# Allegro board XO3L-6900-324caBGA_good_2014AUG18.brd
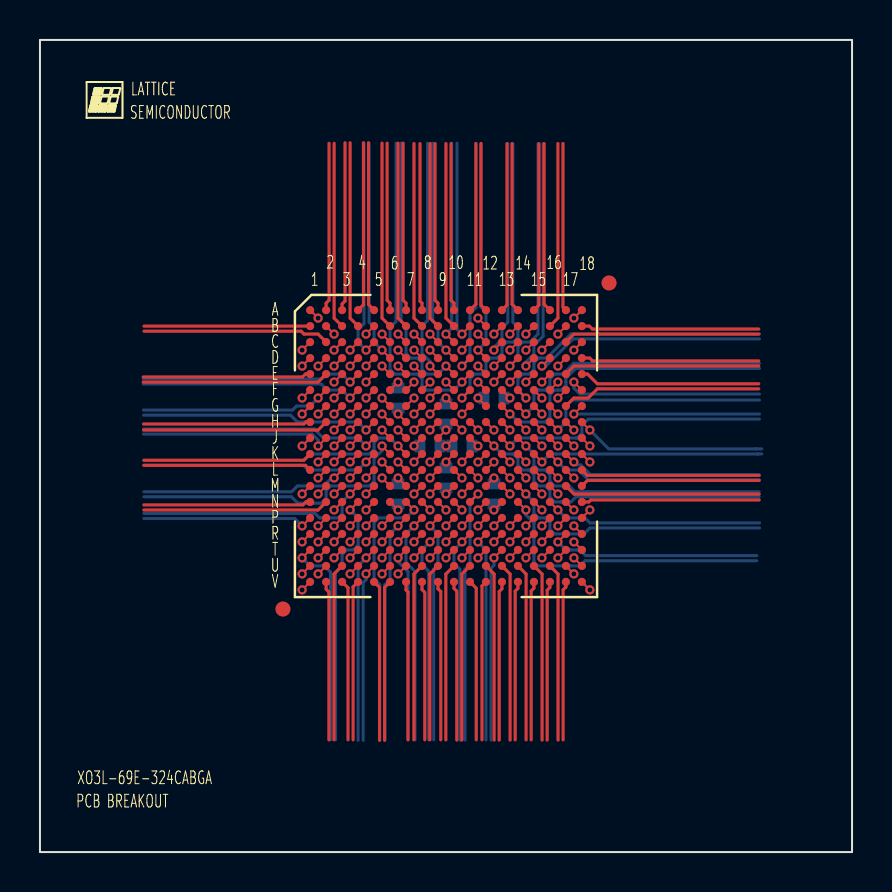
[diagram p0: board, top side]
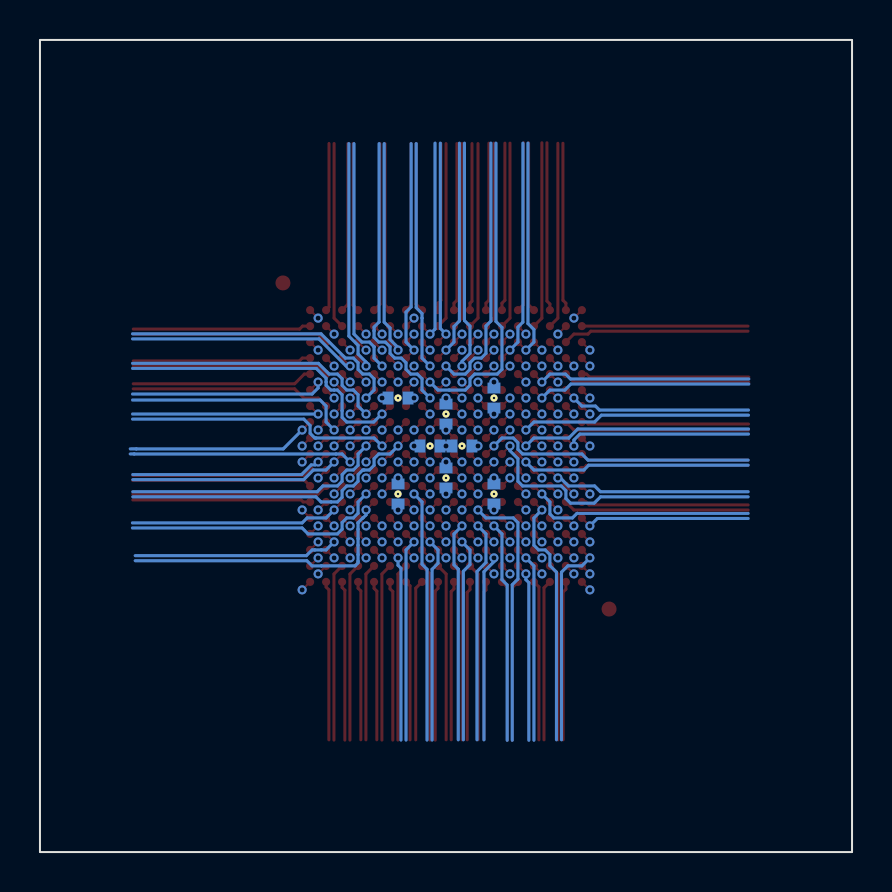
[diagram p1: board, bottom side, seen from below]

Outline 40.64 x 40.64 mm; copper layers: TOP, L2_GND, L3_SIGNAL, L4_SIGNAL, L5_PWR, BOTTOM. Coordinates in mm from the lower left corner of the outline.
Outline path: rectangle 0,0 40.64,40.64

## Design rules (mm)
net group CDPB4: nets PB4C PB4D
net group CDPB6: nets PB6C PB6D
net group CDPB7: nets PB7C PB7D
net group CDPB9: nets PB9C PB9D
net group CDPB13: nets PB13C PB13D
net group CDPB15: nets PB15C PB15D
net group CDPB16: nets PB16C PB16D
net group CDPB18: nets PB18C PB18D
net group CDPB21: nets PB21C PB21D
net group CDPB23: nets PB23C PB23D
net group CDPB26: nets PB26C PB26D
net group CDPB31: nets PB31C PB31D
net group CDPB35: nets PB35C PB35D
net group CDPB37: nets PB37C PB37D
net group CDPB38: nets PB38C PB38D
net group CDPL2: nets PL2C PL2D
net group CDPL3: nets PL3C PL3D
net group CDPL4: nets PL4C PL4D
net group CDPL5: nets PL5C PL5D
net group CDPL6: nets PL6C PL6D
net group CDPL7: nets PL7C PL7D
net group CDPL9: nets PL9C PL9D
net group CDPL10: nets PL10C PL10D
net group CDPL15: nets PL15C PL15D
net group CDPL16: nets PL16C PL16D
net group CDPL18: nets PL18C PL18D
net group CDPL19: nets PL19C PL19D
net group CDPL21: nets PL21C PL21D
net group CDPL23: nets PL23C PL23D
net group CDPL24: nets PL24C PL24D
net group CDPL25: nets PL25C PL25D
net group CDPR2: nets PR2C PR2D
net group CDPR3: nets PR3C PR3D
net group CDPR4: nets PR4C PR4D
net group CDPR6: nets PR6C PR6D
net group CDPR7: nets PR7C PR7D
net group CDPR8: nets PR8C PR8D
net group CDPR10: nets PR10C PR10D
net group CDPR11: nets PR11C PR11D
net group CDPR16: nets PR16C PR16D
net group CDPR17: nets PR17C PR17D
net group CDPR19: nets PR19C PR19D
net group CDPR21: nets PR21C PR21D
net group CDPR22: nets PR22C PR22D
net group CDPR23: nets PR23C PR23D
net group CDPR24: nets PR24C PR24D
net group CDPR25: nets PR25C PR25D
net group CDPT9: nets PT9C PT9D
net group CDPT10: nets PT10C PT10D
net group CDPT11: nets PT11C PT11D
net group CDPT14: nets PT14C PT14D
net group CDPT17: nets PT17C PT17D
net group CDPT18: nets PT18C PT18D
net group CDPT21: nets PT21C PT21D
net group CDPT22: nets PT22C PT22D
net group CDPT25: nets PT25C PT25D
net group CDPT26: nets PT26C PT26D
net group CDPT27: nets PT27C PT27D
net group CDPT33: nets PT33C PT33D
net group CDPT34: nets PT34C PT34D
net group CDPT35: nets PT35C PT35D
net group CDPT36: nets PT36C PT36D
net group PB4: nets PB4A PB4B
net group PB6: nets PB6A PB6B
net group PB7: nets PB7A PB7B
net group PB9: nets PB9A PB9B
net group PB10: nets PB10A PB10B
net group PB12: nets PB12A PB12B
net group PB13: nets PB13A PB13B
net group PB15: nets PB15A PB15B
net group PB16: nets PB16A PB16B
net group PB18: nets PB18A PB18B
net group PB21: nets PB21A PB21B
net group PB23: nets PB23A PB23B
net group PB26: nets PB26A PB26B
net group PB28: nets PB28A PB28B
net group PB29: nets PB29A PB29B
net group PB31: nets PB31A PB31B
net group PB32: nets PB32A PB32B
net group PB34: nets PB34A PB34B
net group PB35: nets PB35A PB35B
net group PB37: nets PB37A PB37B
net group PB38: nets PB38A PB38B
net group PL2: nets PL2A PL2B
net group PL3: nets PL3A PL3B
net group PL4: nets PL4A PL4B
net group PL5: nets PL5A PL5B
net group PL6: nets PL6A PL6B
net group PL8: nets PL8A PL8B
net group PL9: nets PL9A PL9B
net group PL10: nets PL10A PL10B
net group PL11: nets PL11A PL11B
net group PL12: nets PL12A PL12B
net group PL15: nets PL15A PL15B
net group PL17: nets PL17A PL17B
net group PL18: nets PL18A PL18B
net group PL19: nets PL19A PL19B
net group PL22: nets PL22A PL22B
net group PL23: nets PL23A PL23B
net group PL24: nets PL24A PL24B
net group PL25: nets PL25A PL25B
net group PR2: nets PR2A PR2B
net group PR3: nets PR3A PR3B
net group PR4: nets PR4A PR4B
net group PR5: nets PR5A PR5B
net group PR7: nets PR7A PR7B
net group PR8: nets PR8A PR8B
net group PR9: nets PR9A PR9B
net group PR11: nets PR11A PR11B
net group PR12: nets PR12A PR12B
net group PR15: nets PR15A PR15B
net group PR16: nets PR16A PR16B
net group PR17: nets PR17A PR17B
net group PR18: nets PR18A PR18B
net group PR21: nets PR21A PR21B
net group PR22: nets PR22A PR22B
net group PR23: nets PR23A PR23B
net group PR24: nets PR24A PR24B
net group PR25: nets PR25A PR25B
net group PT9: nets PT9A PT9B
net group PT10: nets PT10A PT10B
net group PT11: nets PT11A PT11B
net group PT12: nets PT12A PT12B
net group PT13: nets PT13A PT13B
net group PT14: nets PT14A PT14B
net group PT15: nets PT15A PT15B
net group PT16: nets PT16A PT16B
net group PT17: nets PT17A PT17B
net group PT18: nets PT18A PT18B
net group PT21: nets PT21A PT21B
net group PT22: nets PT22A PT22B
net group PT25: nets PT25A PT25B
net group PT26: nets PT26A PT26B
net group PT27: nets PT27A PT27B
net group PT28: nets PT28A PT28B
net group PT32: nets PT32A PT32B
net group PT33: nets PT33A PT33B
net group PT34: nets PT34A PT34B
net group PT35: nets PT35A PT35B
net group PT36: nets PT36A PT36B

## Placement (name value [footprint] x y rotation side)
BGA  -  [BGA324C80P18X18_1500X1500X17-1]  20.32 20.32 270 top
C1  VAL  [C0402]  17.92 22.72 90 bottom
C2  VAL  [C0402]  20.32 21.92 270 bottom
C3  VAL  [C0402]  22.72 17.92 270 bottom
C4  VAL  [C0402]  22.72 22.72 0 bottom
C5  VAL  [C0402]  19.52 20.32 0 bottom
C6  VAL  [C0402]  21.12 20.32 180 bottom
C7  VAL  [C0402]  20.32 18.72 90 bottom
C8  VAL  [C0402]  17.92 17.92 270 bottom
NOREF  -  []  24.69 13 0 top

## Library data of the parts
BGA = BGA324C80P18X18_1500X1500X17-1
C1-C8 = C0402: User Part Number: UPN; Tolerance: TOL

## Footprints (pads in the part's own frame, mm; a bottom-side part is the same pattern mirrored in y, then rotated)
BGA324C80P18X18_1500X1500X17-1
  round 0.75 smd: (-8.16,8.16) (8.16,-8.16)
  round 0.406 smd: A1(-6.8,-6.8) A2(-6.8,-6) A3(-6.8,-5.2) A4(-6.8,-4.4) A5(-6.8,-3.6) A6(-6.8,-2.8) A7(-6.8,-2) A8(-6.8,-1.2) A9(-6.8,-0.4) A10(-6.8,0.4) A11(-6.8,1.2) A12(-6.8,2) A13(-6.8,2.8) A14(-6.8,3.6) A15(-6.8,4.4) A16(-6.8,5.2) A17(-6.8,6) A18(-6.8,6.8) B1(-6,-6.8) B2(-6,-6) B3(-6,-5.2) B4(-6,-4.4) B5(-6,-3.6) B6(-6,-2.8) B7(-6,-2) B8(-6,-1.2) B9(-6,-0.4) B10(-6,0.4) B11(-6,1.2) B12(-6,2) B13(-6,2.8) B14(-6,3.6) B15(-6,4.4) B16(-6,5.2) B17(-6,6) B18(-6,6.8) C1(-5.2,-6.8) C2(-5.2,-6) C3(-5.2,-5.2) C4(-5.2,-4.4) C5(-5.2,-3.6) C6(-5.2,-2.8) C7(-5.2,-2) C8(-5.2,-1.2) C9(-5.2,-0.4) C10(-5.2,0.4) C11(-5.2,1.2) C12(-5.2,2) C13(-5.2,2.8) C14(-5.2,3.6) C15(-5.2,4.4) C16(-5.2,5.2) C17(-5.2,6) C18(-5.2,6.8) D1(-4.4,-6.8) D2(-4.4,-6) D3(-4.4,-5.2) D4(-4.4,-4.4) D5(-4.4,-3.6) D6(-4.4,-2.8) D7(-4.4,-2) D8(-4.4,-1.2) D9(-4.4,-0.4) D10(-4.4,0.4) D11(-4.4,1.2) D12(-4.4,2) D13(-4.4,2.8) D14(-4.4,3.6) D15(-4.4,4.4) D16(-4.4,5.2) D17(-4.4,6) D18(-4.4,6.8) E1(-3.6,-6.8) E2(-3.6,-6) E3(-3.6,-5.2) E4(-3.6,-4.4) E5(-3.6,-3.6) E6(-3.6,-2.8) E7(-3.6,-2) E8(-3.6,-1.2) E9(-3.6,-0.4) E10(-3.6,0.4) E11(-3.6,1.2) E12(-3.6,2) E13(-3.6,2.8) E14(-3.6,3.6) E15(-3.6,4.4) E16(-3.6,5.2) E17(-3.6,6) E18(-3.6,6.8) F1(-2.8,-6.8) F2(-2.8,-6) F3(-2.8,-5.2) F4(-2.8,-4.4) F5(-2.8,-3.6) F6(-2.8,-2.8) F7(-2.8,-2) F8(-2.8,-1.2) F9(-2.8,-0.4) F10(-2.8,0.4) F11(-2.8,1.2) F12(-2.8,2) F13(-2.8,2.8) F14(-2.8,3.6) F15(-2.8,4.4) F16(-2.8,5.2) F17(-2.8,6) F18(-2.8,6.8) G1(-2,-6.8) G2(-2,-6) G3(-2,-5.2) G4(-2,-4.4) G5(-2,-3.6) G6(-2,-2.8) G7(-2,-2) G8(-2,-1.2) G9(-2,-0.4) G10(-2,0.4) G11(-2,1.2) G12(-2,2) G13(-2,2.8) G14(-2,3.6) G15(-2,4.4) G16(-2,5.2) G17(-2,6) G18(-2,6.8) H1(-1.2,-6.8) H2(-1.2,-6) H3(-1.2,-5.2) H4(-1.2,-4.4) H5(-1.2,-3.6) H6(-1.2,-2.8) H7(-1.2,-2) H8(-1.2,-1.2) H9(-1.2,-0.4) H10(-1.2,0.4) H11(-1.2,1.2) H12(-1.2,2) H13(-1.2,2.8) H14(-1.2,3.6) H15(-1.2,4.4) H16(-1.2,5.2) H17(-1.2,6) H18(-1.2,6.8) J1(-0.4,-6.8) J2(-0.4,-6) J3(-0.4,-5.2) J4(-0.4,-4.4) J5(-0.4,-3.6) J6(-0.4,-2.8) J7(-0.4,-2) J8(-0.4,-1.2) J9(-0.4,-0.4) J10(-0.4,0.4) J11(-0.4,1.2) J12(-0.4,2) J13(-0.4,2.8) J14(-0.4,3.6) J15(-0.4,4.4) J16(-0.4,5.2) J17(-0.4,6) J18(-0.4,6.8) K1(0.4,-6.8) K2(0.4,-6) K3(0.4,-5.2) K4(0.4,-4.4) K5(0.4,-3.6) K6(0.4,-2.8) K7(0.4,-2) K8(0.4,-1.2) K9(0.4,-0.4) K10(0.4,0.4) K11(0.4,1.2) K12(0.4,2) K13(0.4,2.8) K14(0.4,3.6) K15(0.4,4.4) K16(0.4,5.2) K17(0.4,6) K18(0.4,6.8) L1(1.2,-6.8) L2(1.2,-6) L3(1.2,-5.2) L4(1.2,-4.4) L5(1.2,-3.6) L6(1.2,-2.8) L7(1.2,-2) L8(1.2,-1.2) L9(1.2,-0.4) L10(1.2,0.4) L11(1.2,1.2) L12(1.2,2) L13(1.2,2.8) L14(1.2,3.6) L15(1.2,4.4) L16(1.2,5.2) L17(1.2,6) L18(1.2,6.8) M1(2,-6.8) M2(2,-6) M3(2,-5.2) M4(2,-4.4) M5(2,-3.6) M6(2,-2.8) M7(2,-2) M8(2,-1.2) M9(2,-0.4) M10(2,0.4) M11(2,1.2) M12(2,2) M13(2,2.8) M14(2,3.6) M15(2,4.4) M16(2,5.2) M17(2,6) M18(2,6.8) N1(2.8,-6.8) N2(2.8,-6) N3(2.8,-5.2) N4(2.8,-4.4) N5(2.8,-3.6) N6(2.8,-2.8) N7(2.8,-2) N8(2.8,-1.2) N9(2.8,-0.4) N10(2.8,0.4) N11(2.8,1.2) N12(2.8,2) N13(2.8,2.8) N14(2.8,3.6) N15(2.8,4.4) N16(2.8,5.2) N17(2.8,6) N18(2.8,6.8) P1(3.6,-6.8) P2(3.6,-6) P3(3.6,-5.2) P4(3.6,-4.4) P5(3.6,-3.6) P6(3.6,-2.8) P7(3.6,-2) P8(3.6,-1.2) P9(3.6,-0.4) P10(3.6,0.4) P11(3.6,1.2) P12(3.6,2) P13(3.6,2.8) P14(3.6,3.6) P15(3.6,4.4) P16(3.6,5.2) P17(3.6,6) P18(3.6,6.8) R1(4.4,-6.8) R2(4.4,-6) R3(4.4,-5.2) R4(4.4,-4.4) R5(4.4,-3.6) R6(4.4,-2.8) R7(4.4,-2) R8(4.4,-1.2) R9(4.4,-0.4) R10(4.4,0.4) R11(4.4,1.2) R12(4.4,2) R13(4.4,2.8) R14(4.4,3.6) R15(4.4,4.4) R16(4.4,5.2) R17(4.4,6) R18(4.4,6.8) T1(5.2,-6.8) T2(5.2,-6) T3(5.2,-5.2) T4(5.2,-4.4) T5(5.2,-3.6) T6(5.2,-2.8) T7(5.2,-2) T8(5.2,-1.2) T9(5.2,-0.4) T10(5.2,0.4) T11(5.2,1.2) T12(5.2,2) T13(5.2,2.8) T14(5.2,3.6) T15(5.2,4.4) T16(5.2,5.2) T17(5.2,6) T18(5.2,6.8) U1(6,-6.8) U2(6,-6) U3(6,-5.2) U4(6,-4.4) U5(6,-3.6) U6(6,-2.8) U7(6,-2) U8(6,-1.2) U9(6,-0.4) U10(6,0.4) U11(6,1.2) U12(6,2) U13(6,2.8) U14(6,3.6) U15(6,4.4) U16(6,5.2) U17(6,6) U18(6,6.8) V1(6.8,-6.8) V2(6.8,-6) V3(6.8,-5.2) V4(6.8,-4.4) V5(6.8,-3.6) V6(6.8,-2.8) V7(6.8,-2) V8(6.8,-1.2) V9(6.8,-0.4) V10(6.8,0.4) V11(6.8,1.2) V12(6.8,2) V13(6.8,2.8) V14(6.8,3.6) V15(6.8,4.4) V16(6.8,5.2) V17(6.8,6) V18(6.8,6.8)
C0402
  rect 0.54x0.64 smd: 1(-0.5,0) 2(0.5,0)

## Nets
GND: BGA.A1 BGA.A18 BGA.B2 BGA.B17 BGA.F6 BGA.F13 BGA.J9 BGA.J10 BGA.K9 BGA.K10 BGA.N6 BGA.N13 BGA.U2 BGA.U17 BGA.V1 BGA.V18 C1.2 C2.2 C3.2 C4.2 C5.2 C6.2 C7.2 C8.2
VCC: BGA.G12 BGA.H8 BGA.H9 BGA.H10 BGA.H11 BGA.L8 BGA.L9 BGA.L10 BGA.L11 BGA.M12 C3.1 C4.1
VCCIO0: BGA.G8 BGA.G9 BGA.G10 BGA.G11 C2.1
VCCIO1: BGA.H12 BGA.J11 BGA.K11 BGA.L12 C6.1
VCCIO2: BGA.M8 BGA.M9 BGA.M10 BGA.M11 C7.1
VCCIO3: BGA.L7 BGA.M7 C8.1
VCCIO4: BGA.J8 BGA.K8 C5.1
VCCIO5: BGA.G7 BGA.H7 C1.1
PB4A: BGA.V2
PB4B: BGA.U3
PB4C: BGA.R4
PB4D: BGA.P6
PB6A: BGA.T3
PB6B: BGA.U4
PB6C: BGA.P5
PB6D: BGA.R6
PB7A: BGA.V3
PB7B: BGA.V4
PB7C: BGA.R5
PB7D: BGA.T4
PB9A: BGA.T5
PB9B: BGA.U5
PB9C: BGA.N7
PB9D: BGA.P7
PB10A: BGA.N8
PB10B: BGA.R7
PB12A: BGA.T6
PB12B: BGA.U6
PB13A: BGA.V5
PB13B: BGA.V6
PB13C: BGA.T7
PB13D: BGA.P8
PB15A: BGA.V7
PB15B: BGA.U8
PB15C: BGA.U7
PB15D: BGA.R8
PB16A: BGA.T8
PB16B: BGA.T9
PB16C: BGA.R9
PB16D: BGA.P9
PB18A: BGA.V8
PB18B: BGA.U9
PB18C: BGA.N9
PB18D: BGA.N10
PB21A: BGA.V9
PB21B: BGA.U10
PB21C: BGA.T10
PB21D: BGA.R10
PB23A: BGA.V10
PB23B: BGA.U11
PB23C: BGA.P10
PB23D: BGA.T11
PB26A: BGA.V11
PB26B: BGA.V12
PB26C: BGA.N11
PB26D: BGA.R11
PB28A: BGA.P11
PB28B: BGA.T12
PB29A: BGA.U12
PB29B: BGA.V13
PB31A: BGA.U13
PB31B: BGA.V14
PB31C: BGA.R12
PB31D: BGA.T13
PB32A: BGA.T14
PB32B: BGA.N12
PB34A: BGA.U14
PB34B: BGA.V15
PB35A: BGA.U15
PB35B: BGA.V16
PB35C: BGA.P12
PB35D: BGA.R14
PB37A: BGA.T15
PB37B: BGA.T16
PB37C: BGA.R13
PB37D: BGA.R15
PB38A: BGA.U16
PB38B: BGA.V17
PB38C: BGA.P13
PB38D: BGA.P14
PL2A: BGA.B1
PL2B: BGA.C2
PL2C: BGA.D3
PL2D: BGA.C1
PL3A: BGA.E4
PL3B: BGA.F4
PL3C: BGA.E3
PL3D: BGA.F5
PL4A: BGA.D2
PL4B: BGA.G5
PL4C: BGA.F3
PL4D: BGA.D1
PL5A: BGA.E2
PL5B: BGA.E1
PL5C: BGA.F2
PL5D: BGA.H5
PL6A: BGA.G4
PL6B: BGA.G3
PL6C: BGA.F1
PL6D: BGA.G6
PL7C: BGA.H3
PL7D: BGA.H4
PL8A: BGA.G2
PL8B: BGA.G1
PL9A: BGA.H2
PL9B: BGA.H1
PL9C: BGA.H6
PL9D: BGA.J1
PL10A: BGA.J2
PL10B: BGA.J5
PL10C: BGA.J3
PL10D: BGA.J7
PL11A: BGA.J4
PL11B: BGA.K3
PL12A: BGA.K2
PL12B: BGA.J6
PL15A: BGA.K1
PL15B: BGA.L1
PL15C: BGA.K7
PL15D: BGA.K5
PL16C: BGA.K6
PL16D: BGA.L3
PL17A: BGA.K4
PL17B: BGA.L2
PL18A: BGA.L4
PL18B: BGA.M2
PL18C: BGA.M1
PL18D: BGA.L6
PL19A: BGA.N1
PL19B: BGA.N2
PL19C: BGA.M3
PL19D: BGA.L5
PL21C: BGA.M5
PL21D: BGA.N3
PL22A: BGA.P1
PL22B: BGA.M4
PL23A: BGA.R1
PL23B: BGA.P3
PL23C: BGA.P2
PL23D: BGA.M6
PL24A: BGA.N4
PL24B: BGA.T1
PL24C: BGA.R2
PL24D: BGA.U1
PL25A: BGA.T2
PL25B: BGA.N5
PL25C: BGA.P4
PL25D: BGA.R3
PR2A: BGA.B18
PR2B: BGA.C17
PR2C: BGA.F14
PR2D: BGA.D16
PR3A: BGA.E15
PR3B: BGA.C18
PR3C: BGA.G13
PR3D: BGA.G14
PR4A: BGA.F15
PR4B: BGA.D17
PR4C: BGA.E16
PR4D: BGA.H13
PR5A: BGA.G15
PR5B: BGA.F16
PR6C: BGA.E17
PR6D: BGA.D18
PR7A: BGA.G16
PR7B: BGA.H15
PR7C: BGA.H14
PR7D: BGA.F17
PR8A: BGA.E18
PR8B: BGA.G17
PR8C: BGA.H16
PR8D: BGA.F18
PR9A: BGA.J15
PR9B: BGA.H17
PR10C: BGA.J13
PR10D: BGA.G18
PR11A: BGA.J16
PR11B: BGA.J17
PR11C: BGA.J14
PR11D: BGA.J12
PR12A: BGA.H18
PR12B: BGA.K15
PR15A: BGA.K14
PR15B: BGA.J18
PR16A: BGA.K16
PR16B: BGA.K17
PR16C: BGA.K12
PR16D: BGA.K13
PR17A: BGA.K18
PR17B: BGA.L16
PR17C: BGA.L15
PR17D: BGA.L13
PR18A: BGA.L17
PR18B: BGA.M16
PR19C: BGA.L18
PR19D: BGA.M18
PR21A: BGA.M17
PR21B: BGA.N18
PR21C: BGA.L14
PR21D: BGA.N17
PR22A: BGA.M15
PR22B: BGA.P18
PR22C: BGA.M14
PR22D: BGA.N16
PR23A: BGA.P17
PR23B: BGA.N15
PR23C: BGA.R18
PR23D: BGA.M13
PR24A: BGA.P16
PR24B: BGA.T18
PR24C: BGA.R17
PR24D: BGA.N14
PR25A: BGA.P15
PR25B: BGA.U18
PR25C: BGA.R16
PR25D: BGA.T17
PT9A: BGA.A2
PT9B: BGA.B3
PT9C: BGA.D4
PT9D: BGA.E5
PT10A: BGA.C3
PT10B: BGA.C4
PT10C: BGA.F7
PT10D: BGA.E6
PT11A: BGA.A3
PT11B: BGA.B4
PT11C: BGA.D5
PT11D: BGA.B5
PT12A: BGA.A4
PT12B: BGA.A5
PT13A: BGA.C5
PT13B: BGA.D6
PT14A: BGA.B6
PT14B: BGA.A6
PT14C: BGA.D7
PT14D: BGA.C6
PT15A: BGA.A7
PT15B: BGA.B7
PT16A: BGA.D8
PT16B: BGA.E7
PT17A: BGA.B8
PT17B: BGA.A8
PT17C: BGA.C7
PT17D: BGA.C8
PT18A: BGA.A9
PT18B: BGA.B9
PT18C: BGA.E8
PT18D: BGA.F8
PT21A: BGA.A10
PT21B: BGA.B10
PT21C: BGA.C9
PT21D: BGA.D9
PT22A: BGA.C10
PT22B: BGA.B11
PT22C: BGA.E9
PT22D: BGA.D10
PT25A: BGA.B12
PT25B: BGA.C11
PT25C: BGA.F9
PT25D: BGA.F10
PT26A: BGA.A11
PT26B: BGA.A12
PT26C: BGA.E10
PT26D: BGA.E11
PT27A: BGA.C12
PT27B: BGA.B13
PT27C: BGA.D11
PT27D: BGA.D12
PT28A: BGA.A13
PT28B: BGA.A14
PT32A: BGA.F11
PT32B: BGA.C13
PT33A: BGA.B14
PT33B: BGA.B15
PT33C: BGA.E12
PT33D: BGA.F12
PT34A: BGA.C14
PT34B: BGA.C15
PT34C: BGA.D13
PT34D: BGA.E13
PT35A: BGA.A15
PT35B: BGA.A16
PT35C: BGA.D14
PT35D: BGA.D15
PT36A: BGA.B16
PT36B: BGA.A17
PT36C: BGA.C16
PT36D: BGA.E14

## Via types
v1: diameter 0.457, hole 0.254, TOP to BOTTOM, 254 vias

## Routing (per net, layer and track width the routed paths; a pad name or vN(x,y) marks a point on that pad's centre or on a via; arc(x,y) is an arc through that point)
GND: length 11.5
  TOP w0.102: BGA.J10 v1(20.32,20.32) ; BGA.U2 v1(13.92,13.92) ; BGA.V18 v1(27.52,13.12) ; BGA.A1 v1(13.92,26.72) ; BGA.J9 v1(20.32,21.12) ; BGA.U17 v1(26.72,13.92) ; BGA.N6 v1(17.92,17.12) ; BGA.B2 v1(14.72,25.92) ; BGA.F13 v1(23.52,22.72) ; BGA.F6 v1(17.92,23.52) ; BGA.K10 v1(20.32,19.52) ; BGA.B17 v1(25.92,25.92) ; BGA.N13 v1(22.72,17.12) ; BGA.A18 v1(26.72,26.72) ; BGA.K9 v1(19.52,19.52) ; BGA.V1 v1(13.12,13.12)
  BOTTOM w0.102: C3.2 v1(22.72,17.12) ; C1.2 v1(17.92,23.52) ; C6.2 v1(20.32,20.32) C5.2 ; C2.2 v1(20.32,21.12) ; C7.2 v1(20.32,19.52) ; C4.2 v1(23.52,22.72) ; C8.2 v1(17.92,17.12)
VCC: length 6.3
  TOP w0.102: BGA.H9 v1(19.52,21.12) ; BGA.L9 v1(19.52,18.72) ; BGA.L10 v1(21.12,18.72) ; BGA.L11 v1(21.92,18.72) ; BGA.M12 v1(22.72,18.72) ; BGA.H8 v1(18.72,21.12) ; BGA.L8 v1(18.72,18.72) ; BGA.H10 v1(21.12,21.12) ; BGA.H11 v1(21.92,21.12) ; BGA.G12 v1(21.92,22.72)
  BOTTOM w0.102: C4.1 v1(21.92,22.72) ; C3.1 v1(22.72,18.72)
VCCIO0: length 2.6
  TOP w0.102: BGA.G9 v1(19.52,21.92) ; BGA.G11 v1(21.12,21.92) ; BGA.G10 v1(20.32,22.72) ; BGA.G8 v1(18.72,21.92)
  BOTTOM w0.102: C2.1 v1(20.32,22.72)
VCCIO1: length 2.6
  TOP w0.102: BGA.K11 v1(21.12,19.52) ; BGA.J11 v1(21.92,20.32) ; BGA.H12 v1(22.72,21.12) ; BGA.L12 v1(22.72,19.52)
  BOTTOM w0.102: C6.1 v1(21.92,20.32)
VCCIO2: length 2.6
  TOP w0.102: BGA.M10 v1(20.32,17.92) ; BGA.M11 v1(21.12,17.92) ; BGA.M8 v1(18.72,17.92) ; BGA.M9 v1(19.52,17.92)
  BOTTOM w0.102: C7.1 v1(20.32,17.92)
VCCIO3: length 1.4
  TOP w0.102: BGA.M7 v1(17.92,18.72) ; BGA.L7 v1(17.92,19.52)
  BOTTOM w0.102: v1(17.92,18.72) C8.1
VCCIO4: length 1.4
  TOP w0.102: BGA.K8 v1(18.72,19.52) ; BGA.J8 v1(18.72,20.32)
  BOTTOM w0.102: v1(18.72,20.32) C5.1
VCCIO5: length 1.4
  TOP w0.102: BGA.H7 v1(17.92,21.92) ; BGA.G7 v1(18.72,22.72)
  BOTTOM w0.102: C1.1 v1(17.92,21.92)
PB4A: length 8
  TOP w0.152: 14.46,5.62 14.46,13.01 14.32,13.15 BGA.V2
PB4B: length 8.9
  TOP w0.152: 14.71,5.62 14.71,13.91 BGA.U3
PB4C: length 10.7
  TOP w0.102: BGA.R4 v1(15.52,15.52)
  L3_SIGNAL w0.152: 16.2,5.64 16.2,13.47 15.92,13.75 15.92,15.12 v1(15.52,15.52)
PB4D: length 12
  TOP w0.102: BGA.P6 v1(17.12,16.32)
  L3_SIGNAL w0.152: 16.45,5.64 16.45,13.45 16.72,13.72 16.72,14.89 16.95,15.12 17.02,15.12 17.29,15.12 17.52,15.35 17.52,15.92 v1(17.12,16.32)
PB6A: length 9.9
  TOP w0.102: BGA.T3 v1(14.72,14.72)
  L3_SIGNAL w0.152: v1(14.72,14.72) 14.92,14.52 14.92,14.3 14.81,14.19 14.56,13.94 14.56,5.65
PB6B: length 9.7
  TOP w0.102: BGA.U4 v1(15.52,13.92)
  L3_SIGNAL w0.152: v1(15.52,13.92) 15.32,14.12 15.1,14.12 14.99,14.01 14.82,13.84 14.82,5.65
PB6C: length 11.6
  TOP w0.102: BGA.P5 v1(16.32,16.32)
  L4_SIGNAL w0.152: 17,5.59 17,13.35 16.72,13.64 16.72,15.92 v1(16.32,16.32)
PB6D: length 10.8
  TOP w0.102: BGA.R6 v1(17.12,15.52)
  L4_SIGNAL w0.152: 17.26,5.59 17.26,13.31 17.52,13.58 17.52,14.55 17.52,15.11 17.12,15.51 v1(17.12,15.52)
PB7A: length 8
  TOP w0.152: 15.42,5.62 15.42,13.22 BGA.V3
PB7B: length 8
  TOP w0.152: BGA.V4 15.67,13.27 15.67,5.62
PB7C: length 10.8
  TOP w0.102: BGA.R5 v1(16.32,15.52)
  L4_SIGNAL w0.152: v1(16.32,15.52) 16.17,15.52 15.92,15.27 15.92,13.61 15.72,13.41 15.72,5.59
PB7D: length 10
  TOP w0.102: BGA.T4 v1(15.52,14.72)
  L4_SIGNAL w0.152: 15.45,5.62 15.45,13.33 15.12,13.66 15.12,14.32 v1(15.52,14.72)
PB9A: length 9.9
  TOP w0.102: BGA.T5 v1(16.32,14.72)
  BOTTOM w0.152: v1(16.32,14.72) 15.92,14.32 15.92,5.59
PB9B: length 9
  TOP w0.102: BGA.U5 v1(16.32,13.92)
  BOTTOM w0.152: v1(16.32,13.92) 16.32,13.63 16.17,13.48 16.17,5.59
PB9C: length 13.8
  TOP w0.102: BGA.N7 v1(18.72,17.12)
  BOTTOM w0.152: 17.01,5.59 17.01,13.38 16.72,13.66 16.72,16.49 16.95,16.72 18.32,16.72 v1(18.72,17.12)
PB9D: length 11.6
  TOP w0.102: BGA.P7 v1(17.92,16.32)
  BOTTOM w0.152: v1(17.92,16.32) 17.52,15.92 17.52,13.63 17.26,13.37 17.26,5.59
PB10A: length 12.4
  TOP w0.102: BGA.N8 v1(19.52,17.12)
  L4_SIGNAL w0.152: v1(19.52,17.12) 19.12,16.72 19.12,14.35 18.86,14.09 18.86,5.59
PB10B: length 10.8
  TOP w0.102: BGA.R7 v1(17.92,15.52)
  L4_SIGNAL w0.152: v1(17.92,15.52) 18.32,15.12 18.32,14.37 18.6,14.09 18.6,5.59
PB12A: length 9.9
  TOP w0.102: BGA.T6 v1(17.12,14.72)
  L3_SIGNAL w0.152: v1(17.12,14.72) 17.52,14.32 17.52,13.56 17.37,13.42 17.37,5.59
PB12B: length 8.9
  TOP w0.102: v1(17.12,13.92) BGA.U6
  L3_SIGNAL w0.152: v1(17.12,13.92) 17.12,5.59
PB13A: length 8
  TOP w0.152: BGA.V5 16.99,13.25 16.99,5.59
PB13B: length 8
  TOP w0.152: 17.25,5.59 17.25,13.25 BGA.V6
PB13C: length 9.9
  TOP w0.102: BGA.T7 v1(17.92,14.72)
  BOTTOM w0.152: v1(17.92,14.72) 17.92,14.53 18.42,14.03 18.42,5.62
PB13D: length 11.6
  TOP w0.102: BGA.P8 v1(18.72,16.32)
  BOTTOM w0.152: v1(18.72,16.32) 18.32,15.92 18.32,14.49 18.77,14.04 18.77,5.62
PB15A: length 7.9
  TOP w0.152: 18.42,5.62 18.42,13.01 18.32,13.11 BGA.V7
PB15B: length 8.9
  TOP w0.152: BGA.U8 18.71,13.91 18.71,5.62
PB15C: length 8.9
  TOP w0.102: v1(17.92,13.92) BGA.U7
  L3_SIGNAL w0.152: 18.07,5.63 18.07,13.44 17.92,13.59 v1(17.92,13.92)
PB15D: length 10.6
  TOP w0.102: BGA.R8 v1(18.72,15.52)
  L3_SIGNAL w0.152: v1(18.72,15.52) 18.32,15.12 18.32,5.63
PB16A: length 9.8
  TOP w0.102: BGA.T8 v1(18.72,14.72)
  L3_SIGNAL w0.152: 18.97,5.63 18.97,14.47 v1(18.72,14.72)
PB16B: length 9.8
  TOP w0.102: BGA.T9 v1(19.52,14.72)
  L3_SIGNAL w0.152: v1(19.52,14.72) 19.23,14.43 19.23,5.63
PB16C: length 10.8
  TOP w0.102: BGA.R9 v1(19.52,15.52)
  BOTTOM w0.152: 19.45,5.62 19.45,14.05 19.12,14.38 19.12,15.12 v1(19.52,15.52)
PB16D: length 11.5
  TOP w0.102: BGA.P9 v1(19.52,16.32)
  BOTTOM w0.152: v1(19.52,16.32) 19.92,15.92 19.92,14.37 19.71,14.16 19.71,5.62
PB18A: length 8
  TOP w0.152: 19.26,5.62 19.26,12.99 19.12,13.13 BGA.V8
PB18B: length 8.9
  TOP w0.152: 19.51,5.62 19.51,13.91 BGA.U9
PB18C: length 12.4
  TOP w0.102: BGA.N9 v1(20.32,17.12)
  L4_SIGNAL w0.152: 20.22,5.62 20.22,14.18 19.92,14.48 19.92,16.32 19.92,16.32 19.92,16.72 v1(20.32,17.12)
PB18D: length 12.3
  TOP w0.102: BGA.N10 v1(21.12,17.12)
  L4_SIGNAL w0.152: v1(21.12,17.12) 20.72,16.72 20.72,14.37 20.47,14.12 20.47,5.62
PB21A: length 8
  TOP w0.152: 20.06,5.62 20.06,13.04 19.92,13.17 BGA.V9
PB21B: length 8.9
  TOP w0.152: BGA.U10 20.31,13.91 20.31,5.62
PB21C: length 9.7
  TOP w0.102: BGA.T10 v1(20.32,14.72)
  L3_SIGNAL w0.152: 20.17,5.63 20.17,14.28 20.32,14.43 v1(20.32,14.72)
PB21D: length 10.6
  TOP w0.102: BGA.R10 v1(20.32,15.52)
  L3_SIGNAL w0.152: 19.92,5.63 19.92,14.41 19.92,15.12 v1(20.32,15.52)
PB23A: length 8
  TOP w0.152: 20.86,5.6 20.86,13.06 20.72,13.19 BGA.V10
PB23B: length 8.9
  TOP w0.152: 21.11,5.6 21.11,13.91 BGA.U11
PB23C: length 11.4
  TOP w0.102: BGA.P10 v1(20.32,16.32)
  L3_SIGNAL w0.152: 20.72,5.63 20.72,15.92 v1(20.32,16.32)
PB23D: length 9.7
  TOP w0.102: BGA.T11 v1(21.12,14.72)
  L3_SIGNAL w0.152: 20.97,5.63 20.97,14.23 21.12,14.37 v1(21.12,14.72)
PB26A: length 8
  TOP w0.152: BGA.V11 21.83,13.21 21.83,5.62
PB26B: length 8
  TOP w0.152: 22.12,5.62 22.12,13.32 BGA.V12
PB26C: length 13.2
  TOP w0.102: BGA.N11 v1(21.92,17.92)
  BOTTOM w0.152: v1(21.92,17.92) BGA.N11 21.52,14.4 21.27,14.15 21.27,5.6
PB26D: length 10.8
  TOP w0.102: BGA.R11 v1(21.12,15.52)
  BOTTOM w0.152: v1(21.12,15.52) 20.72,15.12 20.72,14.45 21.02,14.15 21.02,5.6
PB28A: length 11.4
  TOP w0.102: BGA.P11 v1(21.12,16.32)
  L3_SIGNAL w0.152: v1(21.12,16.32) 21.52,15.92 21.52,14.33 21.52,5.6
PB28B: length 9.7
  TOP w0.102: BGA.T12 v1(21.92,14.72)
  L3_SIGNAL w0.152: 21.77,5.6 21.77,14.22 21.92,14.37 v1(21.92,14.72)
PB29A: length 8.9
  TOP w0.152: BGA.U12 22.73,13.91 22.73,5.6
PB29B: length 8
  TOP w0.152: 22.98,5.6 22.98,13.04 23.12,13.17 BGA.V13
PB31A: length 8.9
  TOP w0.152: BGA.U13 23.53,13.91 23.53,5.6
PB31B: length 8
  TOP w0.152: 23.78,5.62 23.78,13.06 23.92,13.19 BGA.V14
PB31C: length 10.6
  TOP w0.102: BGA.R12 v1(21.92,15.52)
  BOTTOM w0.152: v1(21.92,15.52) 22.32,15.12 22.32,5.6
PB31D: length 9.7
  TOP w0.102: BGA.T13 v1(22.72,14.72)
  BOTTOM w0.152: 22.57,5.6 22.57,14.2 22.72,14.35 v1(22.72,14.72)
PB32A: length 9.8
  TOP w0.102: BGA.T14 v1(23.52,14.72)
  L3_SIGNAL w0.152: v1(23.52,14.72) 23.52,14.12 23.32,13.92 23.32,5.6
PB32B: length 12.6
  TOP w0.102: BGA.N12 v1(21.92,17.12)
  L3_SIGNAL w0.152: v1(21.92,17.12) 22.32,16.72 22.32,14.55 22.55,14.32 22.57,14.32 23.07,13.82 23.07,5.6
PB34A: length 8.9
  TOP w0.152: 24.33,5.62 24.33,13.91 BGA.U14
PB34B: length 8
  TOP w0.152: 24.58,5.62 24.58,13.07 24.72,13.2 BGA.V15
PB35A: length 8.9
  TOP w0.152: 25.13,5.6 25.13,13.91 BGA.U15
PB35B: length 8
  TOP w0.152: BGA.V16 25.52,13.24 25.38,13.1 25.38,5.6
PB35C: length 11.6
  TOP w0.102: BGA.P12 v1(21.92,16.32)
  L4_SIGNAL w0.152: 21.82,5.62 21.82,14.02 21.52,14.32 21.52,15.92 v1(21.92,16.32)
PB35D: length 12.2
  TOP w0.102: BGA.R14 v1(23.52,15.52)
  L4_SIGNAL w0.152: 22.07,5.62 22.07,14.03 22.32,14.28 22.32,15.69 22.55,15.92 23.12,15.92 v1(23.52,15.52)
PB37A: length 9.8
  TOP w0.102: BGA.T15 v1(24.32,14.72)
  L4_SIGNAL w0.152: 24.58,5.61 24.58,14.46 v1(24.32,14.72)
PB37B: length 9.8
  TOP w0.102: BGA.T16 v1(25.12,14.72)
  L4_SIGNAL w0.152: 24.83,5.61 24.83,14.43 v1(25.12,14.72)
PB37C: length 10.7
  TOP w0.102: BGA.R13 v1(22.72,15.52)
  L4_SIGNAL w0.152: 23.37,5.6 23.37,14.19 23.12,14.44 23.12,15.12 v1(22.72,15.52)
PB37D: length 10.8
  TOP w0.102: BGA.R15 v1(24.32,15.52)
  L4_SIGNAL w0.152: 23.62,5.62 23.62,14.16 23.92,14.46 23.92,15.12 v1(24.32,15.52)
PB38A: length 8.9
  TOP w0.152: 25.93,5.6 25.93,13.91 BGA.U16
PB38B: length 8
  TOP w0.152: BGA.V17 26.32,13.26 26.18,13.13 26.18,5.62
PB38C: length 12.1
  TOP w0.102: BGA.P13 v1(22.72,16.32)
  L3_SIGNAL w0.152: v1(22.72,16.32) 23.12,15.92 23.12,15.69 23.12,15.35 23.35,15.12 23.77,15.12 23.92,14.97 23.92,14.32 24.22,14.02 24.22,5.63
PB38D: length 12.2
  TOP w0.102: BGA.P14 v1(23.52,16.32)
  L3_SIGNAL w0.152: 24.47,5.63 24.47,14.02 24.72,14.27 24.72,15.72 24.52,15.92 24.49,15.92 24.49,15.92 24.15,15.92 24.15,15.92 23.92,15.92 v1(23.52,16.32)
PL2A: length 8.3
  TOP w0.152: BGA.B1 5.21,26.32
PL2B: length 9.3
  TOP w0.152: BGA.C2 13.92,25.92 13.22,25.92 13.07,26.07 5.21,26.07
PL2C: length 10.2
  TOP w0.102: BGA.D3 v1(14.72,24.32)
  L3_SIGNAL w0.152: 5.21,24.72 14.32,24.72 v1(14.72,24.32)
PL2D: length 8.5
  TOP w0.102: BGA.C1 v1(13.12,25.12)
  L3_SIGNAL w0.152: 5.21,24.97 12.71,24.97 12.85,25.12 v1(13.12,25.12)
PL3A: length 11.2
  TOP w0.102: BGA.E4 v1(15.52,23.52)
  BOTTOM w0.152: v1(15.52,23.52) 15.12,23.92 14.34,23.92 14.09,23.67 5.17,23.67
PL3B: length 11.2
  TOP w0.102: BGA.F4 v1(15.52,22.72)
  BOTTOM w0.152: 5.17,23.42 14.07,23.42 14.37,23.12 15.12,23.12 v1(15.52,22.72)
PL3C: length 10.1
  TOP w0.102: BGA.E3 v1(14.72,23.52)
  L3_SIGNAL w0.152: v1(14.72,23.52) 5.17,23.52
PL3D: length 12.5
  TOP w0.102: BGA.F5 v1(16.32,22.72)
  L3_SIGNAL w0.152: 5.17,23.77 14.15,23.77 14.3,23.92 14.89,23.92 15.12,23.69 15.12,23.35 15.35,23.12 15.92,23.12 v1(16.32,22.72)
PL4A: length 10.4
  TOP w0.102: BGA.D2 v1(13.92,24.32)
  L4_SIGNAL w0.152: 5.21,25.22 12.39,25.22 12.79,25.62 13.27,25.62 13.92,24.97 v1(13.92,24.32)
PL4B: length 13.7
  TOP w0.102: BGA.G5 v1(16.32,21.92)
  L4_SIGNAL w0.152: 5.21,24.97 12.37,24.97 12.62,24.72 12.97,24.72 13.29,24.72 13.52,24.49 13.52,24.15 13.75,23.92 14.5,23.92 14.89,23.92 15.12,23.69 15.12,23.35 15.35,23.12 15.69,23.12 15.92,22.89 15.92,22.32 v1(16.32,21.92)
PL4C: length 10.4
  TOP w0.102: BGA.F3 v1(14.72,22.72)
  L4_SIGNAL w0.152: 5.17,23.35 14.09,23.35 v1(14.72,22.72)
PL4D: length 9
  TOP w0.102: BGA.D1 v1(13.12,24.32)
  L4_SIGNAL w0.152: 5.17,23.6 12.8,23.6 13.12,23.92 v1(13.12,24.32)
PL5A: length 9.3
  TOP w0.152: BGA.E2 13.92,23.52 5.17,23.52
PL5B: length 8.4
  TOP w0.152: BGA.E1 13.28,23.92 13.14,23.77 5.17,23.77
PL5C: length 9.6
  TOP w0.102: BGA.F2 v1(13.92,22.72)
  BOTTOM w0.152: 5.18,22.12 12.64,22.12 12.84,22.32 13.52,22.32 v1(13.92,22.72)
PL5D: length 12
  TOP w0.102: BGA.H5 v1(16.32,21.12)
  BOTTOM w0.152: 5.18,21.86 12.54,21.86 12.88,21.52 15.92,21.52 v1(16.32,21.12)
PL6A: length 11.2
  TOP w0.102: BGA.G4 v1(15.52,21.92)
  L4_SIGNAL w0.152: v1(15.52,21.92) 15.12,21.52 12.76,21.52 12.53,21.75 5.18,21.75
PL6B: length 10.4
  TOP w0.102: BGA.G3 v1(14.72,21.92)
  L4_SIGNAL w0.102: 14.72,21.92 v1(14.72,21.92)
  L4_SIGNAL w0.152: 5.18,22 12.55,22 12.87,22.32 14.32,22.32 v1(14.72,21.92)
PL6C: length 8.5
  TOP w0.102: BGA.F1 v1(13.12,22.72)
  L3_SIGNAL w0.152: v1(13.12,22.72) 5.18,22.72
PL6D: length 13.3
  TOP w0.102: BGA.G6 v1(17.12,22.72)
  L3_SIGNAL w0.152: v1(17.12,22.72) 16.72,22.32 14.55,22.32 14.32,22.55 14.32,22.89 14.09,23.12 12.81,23.12 12.67,22.97 5.18,22.97
PL7C: length 10.2
  TOP w0.102: BGA.H3 v1(14.72,21.12)
  L3_SIGNAL w0.152: v1(14.72,21.12) 14.45,21.12 14.3,21.27 5.18,21.27
PL7D: length 11.1
  TOP w0.102: BGA.H4 v1(15.52,21.12)
  L3_SIGNAL w0.152: 5.18,21.52 15.12,21.52 15.52,21.12 v1(15.52,21.12)
PL8A: length 9.5
  TOP w0.102: BGA.G2 v1(13.92,21.92)
  L3_SIGNAL w0.152: v1(13.92,21.92) 13.69,21.92 13.29,22.32 5.18,22.32
PL8B: length 8.6
  TOP w0.102: BGA.G1 v1(13.12,21.92)
  L3_SIGNAL w0.152: v1(13.12,21.92) 12.91,21.92 12.77,22.07 5.18,22.07
PL9A: length 9.3
  TOP w0.152: 5.18,21.12 13.92,21.12 BGA.H2
PL9B: length 8.4
  TOP w0.152: BGA.H1 13.31,21.52 13.21,21.42 5.18,21.42
PL9C: length 13.4
  TOP w0.102: BGA.H6 v1(17.12,21.92)
  L3_SIGNAL w0.152: v1(17.12,21.92) 17.12,21.92 16.72,21.52 16.72,20.92 16.52,20.72 14.55,20.72 5.18,20.72
PL9D: length 8.6
  TOP w0.102: BGA.J1 v1(13.12,20.32)
  L3_SIGNAL w0.152: 5.18,20.47 12.67,20.47 12.82,20.32 v1(13.12,20.32)
PL10A: length 9.7
  TOP w0.102: BGA.J2 v1(13.92,20.32)
  BOTTOM w0.152: v1(13.92,20.32) 13.92,20.62 13.62,20.92 5.18,20.92
PL10B: length 12.1
  TOP w0.102: BGA.J5 v1(16.32,20.32)
  BOTTOM w0.152: 5.18,21.17 13.73,21.17 14.17,20.72 14.17,20.72 15.92,20.72 v1(16.32,20.32)
PL10C: length 10.3
  TOP w0.102: BGA.J3 v1(14.72,20.32)
  L4_SIGNAL w0.152: 5.18,20.83 14.03,20.83 14.54,20.32 v1(14.72,20.32)
PL10D: length 13.6
  TOP w0.102: BGA.J7 v1(17.92,21.12)
  L4_SIGNAL w0.152: 5.18,21.08 14.13,21.08 14.5,20.72 17.52,20.72 v1(17.92,21.12)
PL11A: length 11.2
  TOP w0.102: BGA.J4 v1(15.52,20.32)
  L4_SIGNAL w0.152: 5.2,19.61 13.38,19.61 13.69,19.92 15.12,19.92 v1(15.52,20.32)
PL11B: length 10.4
  TOP w0.102: BGA.K3 v1(14.72,19.52)
  L4_SIGNAL w0.152: v1(14.72,19.52) 14.32,19.12 13.55,19.12 13.31,19.36 5.2,19.36
PL12A: length 9.3
  TOP w0.102: BGA.K2 v1(13.92,19.52)
  L3_SIGNAL w0.152: v1(13.92,19.52) 13.64,19.52 13.5,19.67 5.2,19.67
PL12B: length 14.1
  TOP w0.102: BGA.J6 v1(17.12,21.12)
  L3_SIGNAL w0.152: 5.2,19.92 13.6,19.92 17.32,19.92 17.52,20.12 BGA.J6 v1(17.12,21.12)
PL15A: length 8.5
  TOP w0.152: BGA.K1 13.21,19.61 5.2,19.61
PL15B: length 8.4
  TOP w0.152: BGA.L1 13.29,19.35 5.2,19.35
PL15C: length 14.1
  TOP w0.102: BGA.K7 v1(17.92,20.32)
  BOTTOM w0.152: v1(17.92,20.32) 17.52,20.72 16.95,20.72 16.72,20.49 16.72,20.15 16.49,19.92 13.52,19.92 13.21,19.61 5.2,19.61
PL15D: length 12
  TOP w0.102: BGA.K5 v1(16.32,19.52)
  BOTTOM w0.152: 5.2,19.36 13.18,19.36 13.42,19.12 15.92,19.12 v1(16.32,19.52)
PL16C: length 14.8
  TOP w0.102: BGA.K6 v1(17.12,20.32)
  BOTTOM w0.152: 5.2,17.78 12.59,17.78 12.91,17.46 14.08,17.46 14.32,17.69 14.32,18.09 14.55,18.32 16.49,18.32 16.72,18.55 16.72,19.69 17.12,20.09 v1(17.12,20.32)
PL16D: length 10.4
  TOP w0.102: BGA.L3 v1(14.72,18.72)
  BOTTOM w0.152: 5.2,18.03 12.59,18.03 12.88,18.32 14.2,18.32 14.6,18.72 v1(14.72,18.72)
PL17A: length 11.1
  TOP w0.102: BGA.K4 v1(15.52,19.52)
  L3_SIGNAL w0.152: 5.2,19.12 15.12,19.12 v1(15.52,19.52)
PL17B: length 9.3
  TOP w0.102: BGA.L2 v1(13.92,18.72)
  L3_SIGNAL w0.152: v1(13.92,18.72) 13.53,18.72 13.38,18.87 5.2,18.87
PL18A: length 11.2
  TOP w0.102: BGA.L4 v1(15.52,18.72)
  L4_SIGNAL w0.152: 5.2,18.77 13.3,18.77 13.75,18.32 15.12,18.32 15.52,18.72 v1(15.52,18.72)
PL18B: length 9.5
  TOP w0.102: BGA.M2 v1(13.92,17.92)
  L4_SIGNAL w0.152: v1(13.92,17.92) 13.79,17.92 13.19,18.52 5.2,18.52
PL18C: length 8.5
  TOP w0.102: BGA.M1 v1(13.12,17.92)
  L3_SIGNAL w0.152: v1(13.12,17.92) 12.73,17.92 12.59,18.07 5.2,18.07
PL18D: length 13.3
  TOP w0.102: BGA.L6 v1(17.12,19.52)
  L3_SIGNAL w0.152: 5.2,18.32 16.49,18.32 16.72,18.55 16.72,19.12 v1(17.12,19.52)
PL19A: length 8.4
  TOP w0.152: 5.2,17.37 13.16,17.37 13.31,17.52 BGA.N1
PL19B: length 9.3
  TOP w0.152: BGA.N2 13.92,17.12 5.2,17.12
PL19C: length 10.3
  TOP w0.102: BGA.M3 v1(14.72,17.92)
  L4_SIGNAL w0.152: 5.2,17.44 14.02,17.44 14.5,17.92 v1(14.72,17.92)
PL19D: length 12.7
  TOP w0.102: BGA.L5 v1(16.32,18.72)
  L4_SIGNAL w0.152: 5.2,17.19 14.13,17.19 14.46,17.52 14.79,17.52 15.69,17.52 15.92,17.75 15.92,18.32 v1(16.32,18.72)
PL21C: length 11.9
  TOP w0.102: BGA.M5 v1(16.32,17.92)
  L3_SIGNAL w0.152: v1(16.32,17.92) 15.92,17.52 5.2,17.52
PL21D: length 10.1
  TOP w0.102: BGA.N3 v1(14.72,17.12)
  L3_SIGNAL w0.152: v1(14.72,17.12) 14.38,17.12 14.24,17.27 5.2,17.27
PL22A: length 8.6
  TOP w0.102: BGA.P1 v1(13.12,16.32)
  BOTTOM w0.152: 5.2,16.69 12.75,16.69 v1(13.12,16.32)
PL22B: length 11.8
  TOP w0.102: BGA.M4 v1(15.52,17.92)
  BOTTOM w0.152: 5.2,16.95 13.77,16.95 13.99,16.72 14.92,16.72 15.12,16.92 15.12,17.52 v1(15.52,17.92)
PL23A: length 8.5
  TOP w0.102: BGA.R1 v1(13.12,15.52)
  L3_SIGNAL w0.152: v1(13.12,15.52) 12.83,15.52 12.68,15.67 5.2,15.67
PL23B: length 10.3
  TOP w0.102: BGA.P3 v1(14.72,16.32)
  L3_SIGNAL w0.152: 5.2,15.92 14.02,15.92 14.32,15.92 v1(14.72,16.32)
PL23C: length 9.5
  TOP w0.102: BGA.P2 v1(13.92,16.32)
  L3_SIGNAL w0.152: 5.2,16.57 12.47,16.57 12.63,16.72 13.52,16.72 v1(13.92,16.32)
PL23D: length 14.3
  TOP w0.102: BGA.M6 v1(17.12,18.72)
  L3_SIGNAL w0.152: 5.2,16.82 12.37,16.82 12.52,16.97 13.86,16.97 14.12,16.72 16.57,16.72 16.77,16.92 16.77,18.02 17.12,18.37 v1(17.12,18.72)
PL24A: length 12.9
  TOP w0.102: BGA.N4 v1(15.52,17.12)
  BOTTOM w0.152: 14.79,5.62 14.79,14.01 15.12,14.34 15.12,14.89 15.35,15.12 15.69,15.12 15.92,15.35 15.92,16.72 v1(15.52,17.12)
PL24B: length 10.7
  TOP w0.102: BGA.T1 v1(13.12,14.72)
  BOTTOM w0.152: v1(13.12,14.72) 13.52,14.32 14.23,14.32 14.54,14.01 14.54,5.62
PL24C: length 9.6
  TOP w0.102: BGA.R2 v1(13.92,15.52)
  L3_SIGNAL w0.152: v1(13.92,15.52) 13.52,15.12 13.12,15.12 12.67,15.12 12.31,14.76 5.21,14.76
PL24D: length 8.7
  TOP w0.102: BGA.U1 v1(13.12,13.92)
  L3_SIGNAL w0.152: 5.21,14.5 12.22,14.5 12.81,13.92 v1(13.12,13.92)
PL25A: length 9.6
  TOP w0.102: BGA.T2 v1(13.92,14.72)
  L4_SIGNAL w0.152: v1(13.92,14.72) 13.52,14.32 13.29,14.32 13.29,14.32 12.95,14.32 12.95,14.32 12.82,14.32 12.47,14.67 5.22,14.67
PL25B: length 13.1
  TOP w0.102: BGA.N5 v1(16.32,17.12)
  L4_SIGNAL w0.152: 5.22,14.92 12.52,14.92 12.72,15.12 14.89,15.12 14.89,15.11 15.12,15.34 15.12,15.35 15.12,15.35 15.12,15.69 15.12,15.69 15.12,15.69 15.35,15.92 15.65,15.92 15.69,15.92 15.92,16.15 15.92,16.72 v1(16.32,17.12)
PL25C: length 11.2
  TOP w0.102: BGA.P4 v1(15.52,16.32)
  L4_SIGNAL w0.152: 5.2,16.4 12.53,16.4 12.85,16.72 15.12,16.72 v1(15.52,16.32)
PL25D: length 10.3
  TOP w0.102: BGA.R3 v1(14.72,15.52)
  L4_SIGNAL w0.152: 5.2,16.15 12.55,16.15 12.78,15.92 14.32,15.92 v1(14.72,15.52)
PR2A: length 8.9
  TOP w0.152: BGA.B18 27.5,26.32 27.65,26.17 35.97,26.17
PR2B: length 9.8
  TOP w0.152: 35.97,25.92 26.72,25.92 BGA.C17
PR2C: length 14.9
  TOP w0.102: BGA.F14 v1(24.32,22.72)
  BOTTOM w0.152: v1(24.32,22.72) BGA.F14 23.92,23.69 24.15,23.92 24.49,23.92 24.72,24.15 24.72,24.49 24.95,24.72 25.36,24.72 26.57,25.93 36.01,25.93
PR2D: length 12
  TOP w0.102: BGA.D16 v1(25.12,24.32)
  BOTTOM w0.152: 36.01,25.68 26.68,25.68 25.32,24.32 v1(25.12,24.32)
PR3A: length 13.1
  TOP w0.102: BGA.E15 v1(24.32,23.52)
  L3_SIGNAL w0.152: 35.97,25.06 27.69,25.06 27.34,24.72 25.75,24.72 25.52,24.49 25.52,24.15 25.29,23.92 24.95,23.92 24.55,23.52 v1(24.32,23.52)
PR3B: length 9.9
  TOP w0.102: BGA.C18 v1(26.72,25.12)
  L3_SIGNAL w0.152: 35.97,25.32 27.58,25.32 27.38,25.12 v1(26.72,25.12)
PR3C: length 15.2
  TOP w0.102: BGA.G13 v1(23.52,21.92)
  BOTTOM w0.152: 36.01,24.2 26.81,24.2 26.32,23.71 26.32,23.52 26.32,23.35 26.09,23.12 25.92,23.12 25.75,23.12 25.52,22.89 25.52,22.09 25.52,21.75 25.29,21.52 23.94,21.52 23.54,21.92 v1(23.52,21.92)
PR3D: length 13.8
  TOP w0.102: BGA.G14 v1(24.32,21.92)
  BOTTOM w0.152: 36.01,24.46 26.71,24.46 26.17,23.92 25.75,23.92 25.52,23.69 25.52,23.35 25.29,23.12 24.95,23.12 24.72,22.89 24.72,22.32 v1(24.32,21.92)
PR4A: length 11.8
  TOP w0.102: BGA.F15 v1(25.12,22.72)
  L3_SIGNAL w0.152: v1(25.12,22.72) 25.52,23.12 27.12,23.12 27.59,23.59 35.97,23.59
PR4B: length 10.8
  TOP w0.102: BGA.D17 v1(25.92,24.32)
  L3_SIGNAL w0.152: v1(25.92,24.32) 27.03,24.32 27.5,23.84 35.97,23.84
PR4C: length 11.5
  TOP w0.102: BGA.E16 v1(25.12,23.52)
  L4_SIGNAL w0.152: v1(25.12,23.52) 25.35,23.52 25.75,23.92 26.47,23.92 26.7,24.15 35.77,24.15
PR4D: length 15.8
  TOP w0.102: BGA.H13 v1(23.52,21.12)
  L4_SIGNAL w0.152: 35.77,24.41 26.73,24.41 26.42,24.72 25.75,24.72 25.52,24.49 25.52,24.15 25.29,23.92 24.95,23.92 24.72,23.69 24.72,23.35 24.72,23.35 24.72,22.89 24.72,22.89 24.72,22.55 24.72,22.55 24.72,22.09 24.72,22.09 24.72,21.75 24.72,21.75 24.72,21.67 24.57,21.52 23.92,21.52 v1(23.52,21.12)
PR5A: length 12.5
  TOP w0.102: BGA.G15 v1(25.12,21.92)
  L4_SIGNAL w0.152: 35.99,22.72 26.48,22.72 26.09,23.12 25.67,23.12 25.52,22.97 25.52,22.32 v1(25.12,21.92)
PR5B: length 10.9
  TOP w0.102: BGA.F16 v1(25.92,23.52)
  L4_SIGNAL w0.152: 35.99,22.98 26.59,22.98 26.19,23.37 26.07,23.37 v1(25.92,23.52)
PR6C: length 9.8
  TOP w0.152: 35.97,24.32 26.72,24.32 BGA.E17
PR6D: length 8.9
  TOP w0.152: 35.97,24.58 27.66,24.58 27.51,24.72 BGA.D18
PR7A: length 10.9
  TOP w0.102: BGA.G16 v1(25.92,21.92)
  L4_SIGNAL w0.152: v1(25.92,21.92) 26.32,22.32 27.41,22.32 27.6,22.12 36.01,22.12
PR7B: length 11.8
  TOP w0.102: BGA.H15 v1(25.12,21.12)
  L4_SIGNAL w0.152: v1(25.12,21.12) 25.52,21.52 27.27,21.52 27.62,21.87 36.01,21.87
PR7C: length 13
  TOP w0.102: BGA.H14 v1(24.32,21.12)
  L3_SIGNAL w0.152: v1(24.32,21.12) 24.72,21.52 26.09,21.52 26.32,21.75 26.32,22.18 26.61,22.47 35.97,22.47
PR7D: length 10.6
  TOP w0.102: BGA.F17 v1(25.92,22.72)
  L3_SIGNAL w0.152: v1(25.92,22.72) 35.97,22.72
PR8A: length 9.1
  TOP w0.152: BGA.E18 27.41,23.92 27.89,23.43 35.97,23.43
PR8B: length 10
  TOP w0.152: BGA.G17 26.72,22.72 27.43,22.72 27.89,23.18 35.97,23.18
PR8C: length 11.7
  TOP w0.102: BGA.H16 v1(25.92,21.12)
  BOTTOM w0.152: v1(25.92,21.12) 26.32,21.52 26.32,22.32 26.62,22.62 36.01,22.62
PR8D: length 10.3
  TOP w0.102: BGA.F18 v1(26.72,23.52)
  BOTTOM w0.152: v1(26.72,23.52) 26.72,23.22 27.02,22.92 36.01,22.92
PR9A: length 11.7
  TOP w0.102: BGA.J15 v1(25.12,20.32)
  L3_SIGNAL w0.152: v1(25.12,20.32) 25.52,20.72 27.92,20.72 28.22,21.02 35.98,21.02
PR9B: length 10.1
  TOP w0.102: BGA.H17 v1(26.72,21.12)
  L3_SIGNAL w0.152: 35.98,21.27 28.17,21.27 27.92,21.52 27.12,21.52 26.72,21.12 v1(26.72,21.12)
PR10C: length 13.8
  TOP w0.102: BGA.J13 v1(23.52,20.32)
  BOTTOM w0.152: 36.01,21.67 27.44,21.67 27.12,21.35 27.12,20.95 26.89,20.72 26.82,20.72 23.92,20.72 v1(23.52,20.32)
PR10D: length 9.9
  TOP w0.102: BGA.G18 v1(26.72,21.92)
  BOTTOM w0.152: v1(26.72,21.92) 36.01,21.92
PR11A: length 10.9
  TOP w0.102: BGA.J16 v1(25.92,20.32)
  L4_SIGNAL w0.152: 36,20.22 28.17,20.22 27.87,19.92 26.32,19.92 v1(25.92,20.32)
PR11B: length 10.1
  TOP w0.102: BGA.J17 v1(26.72,20.32)
  L4_SIGNAL w0.152: v1(26.72,20.32) 27.12,20.72 27.86,20.72 28.11,20.47 36,20.47
PR11C: length 13.7
  TOP w0.102: BGA.J14 v1(24.32,20.32)
  BOTTOM w0.152: v1(24.32,20.32) 24.72,19.92 24.72,19.35 24.95,19.12 25.29,19.12 25.52,18.89 25.52,18.55 25.75,18.32 26.48,18.32 26.77,18.03 35.99,18.03
PR11D: length 15.7
  TOP w0.102: BGA.J12 v1(22.72,20.32)
  BOTTOM w0.152: v1(22.72,20.32) 23.12,19.92 23.69,19.92 23.92,19.69 23.92,19.35 24.15,19.12 24.49,19.12 24.72,18.89 24.72,18.55 24.95,18.32 25.29,18.32 25.52,18.09 25.52,17.75 25.75,17.52 26.07,17.52 26.57,17.52 26.83,17.78 35.99,17.78
PR12A: length 9.6
  TOP w0.102: BGA.H18 v1(27.52,21.12)
  BOTTOM w0.152: v1(27.52,21.12) 28.47,20.17 35.82,20.17 35.82,20.18 36.12,20.18
PR12B: length 11.7
  TOP w0.102: BGA.K15 v1(25.12,19.52)
  BOTTOM w0.152: v1(25.12,19.52) 25.52,19.92 25.82,19.92 35.92,19.92 35.93,19.92 36.12,19.92
PR15A: length 12.5
  TOP w0.102: BGA.K14 v1(24.32,19.52)
  L3_SIGNAL w0.152: 36,20.07 28.02,20.07 27.88,19.92 24.72,19.92 v1(24.32,19.52)
PR15B: length 9
  TOP w0.102: BGA.J18 v1(27.52,20.32)
  L3_SIGNAL w0.152: 36,20.32 v1(27.52,20.32)
PR16A: length 11
  TOP w0.102: BGA.K16 v1(25.92,19.52)
  BOTTOM w0.152: v1(25.92,19.52) 26.32,19.12 26.96,19.12 27.44,18.64 35.99,18.64
PR16B: length 10.1
  TOP w0.102: BGA.K17 v1(26.72,19.52)
  BOTTOM w0.152: 35.99,18.89 27.55,18.89 27.06,19.37 26.87,19.37 v1(26.72,19.52)
PR16C: length 20.7
  TOP w0.102: BGA.K12 v1(21.92,19.52)
  L3_SIGNAL w0.152: v1(21.92,19.52) 22.32,19.12 22.89,19.12 23.12,19.35 23.12,22.12 22.12,23.12 22.09,23.12 21.29,23.12 20.49,23.12 20.15,23.12 19.92,23.35 19.92,26.22 20.17,26.47 20.17,35.47
PR16D: length 19.1
  TOP w0.102: BGA.K13 v1(23.52,19.52)
  L3_SIGNAL w0.152: 20.42,35.56 20.42,26.52 20.72,26.22 20.72,25.12 20.72,24.15 20.95,23.92 20.99,23.92 21.29,23.92 22.09,23.92 22.32,23.69 22.32,23.65 22.32,23.35 22.55,23.12 23.35,22.32 23.69,22.32 23.92,22.09 23.92,22.05 23.92,21.75 23.92,20.95 23.92,20.15 23.92,19.92 v1(23.52,19.52)
PR17A: length 9.2
  TOP w0.102: BGA.K18 v1(27.52,19.52)
  L3_SIGNAL w0.152: 35.99,19.12 27.92,19.12 v1(27.52,19.52)
PR17B: length 10.9
  TOP w0.102: BGA.L16 v1(25.92,18.72)
  L3_SIGNAL w0.152: v1(25.92,18.72) 26.32,19.12 27.56,19.12 27.81,18.87 35.99,18.87
PR17C: length 11.7
  TOP w0.102: BGA.L15 v1(25.12,18.72)
  L4_SIGNAL w0.152: 35.99,18.52 27.48,18.52 27.28,18.32 25.52,18.32 v1(25.12,18.72)
PR17D: length 13.3
  TOP w0.102: BGA.L13 v1(23.52,18.72)
  L4_SIGNAL w0.152: 35.99,18.82 27.52,18.82 27.22,19.12 23.92,19.12 v1(23.52,18.72)
PR18A: length 10.8
  TOP w0.102: BGA.L17 v1(26.72,18.72)
  L3_SIGNAL w0.152: v1(26.72,18.72) 26.52,18.52 26.52,18.3 26.66,18.16 26.88,18.16 27.24,18.52 35.99,18.52
PR18B: length 11
  TOP w0.102: BGA.M16 v1(25.92,17.92)
  L3_SIGNAL w0.152: v1(25.92,17.92) 26.12,18.12 26.34,18.12 26.56,17.9 26.98,17.9 27.34,18.27 35.99,18.27
PR19C: length 9
  TOP w0.152: BGA.L18 27.39,18.85 35.99,18.85
PR19D: length 9
  TOP w0.152: 35.99,18.59 27.39,18.59 BGA.M18
PR21A: length 9.8
  TOP w0.152: 35.99,17.91 26.73,17.91 BGA.M17
PR21B: length 8.9
  TOP w0.152: BGA.N18 27.47,17.52 27.57,17.62 35.99,17.62
PR21C: length 13.3
  TOP w0.102: BGA.L14 v1(24.32,18.72)
  L4_SIGNAL w0.152: 35.99,18.01 26.77,18.01 26.28,17.52 24.95,17.52 24.72,17.75 24.72,18.32 v1(24.32,18.72)
PR21D: length 10.4
  TOP w0.102: BGA.N17 v1(26.72,17.12)
  L4_SIGNAL w0.152: v1(26.72,17.12) 26.72,17.57 26.91,17.76 35.99,17.76
PR22A: length 11.8
  TOP w0.102: BGA.M15 v1(25.12,17.92)
  L3_SIGNAL w0.152: v1(25.12,17.92) 25.52,17.52 28.12,17.52 28.47,17.87 35.99,17.87
PR22B: length 9.2
  TOP w0.102: BGA.P18 v1(27.52,17.12)
  L3_SIGNAL w0.152: v1(27.52,17.12) 28.12,17.12 28.62,17.62 35.99,17.62
PR22C: length 13.7
  TOP w0.102: BGA.M14 v1(24.32,17.92)
  BOTTOM w0.152: v1(24.32,17.92) 24.72,17.52 24.72,16.95 24.95,16.72 25.29,16.72 25.52,16.49 25.52,16.15 25.75,15.92 27.22,15.92 27.52,16.22 36.01,16.22
PR22D: length 10.9
  TOP w0.102: BGA.N16 v1(25.92,17.12)
  BOTTOM w0.152: v1(25.92,17.12) 26.32,16.72 27.27,16.72 27.52,16.47 36.01,16.47
PR23A: length 10.9
  TOP w0.102: BGA.P17 v1(25.92,16.32)
  L4_SIGNAL w0.152: v1(25.92,16.32) 26.32,15.92 27.06,15.92 27.31,16.17 27.32,16.16 36.01,16.16
PR23B: length 11.8
  TOP w0.102: BGA.N15 v1(25.12,17.12)
  L4_SIGNAL w0.152: 36.01,16.41 27.42,16.41 27.12,16.72 25.52,16.72 v1(25.12,17.12)
PR23C: length 9.9
  TOP w0.102: BGA.R18 v1(26.72,16.32)
  L3_SIGNAL w0.152: v1(26.72,16.32) 36.01,16.32
PR23D: length 13.8
  TOP w0.102: BGA.M13 v1(23.52,17.92)
  L3_SIGNAL w0.152: 36.01,16.57 27.22,16.57 27.08,16.72 26.09,16.72 25.02,16.72 24.95,16.72 24.72,16.95 24.72,17.02 24.72,17.29 24.49,17.52 24.22,17.52 23.92,17.52 v1(23.52,17.92)
PR24A: length 11.6
  TOP w0.102: BGA.P16 v1(25.12,16.32)
  L3_SIGNAL w0.152: v1(25.12,16.32) 25.12,16.32 25.52,15.92 36.01,15.92
PR24B: length 9.9
  TOP w0.102: BGA.T18 v1(26.72,15.52)
  L3_SIGNAL w0.152: v1(26.72,15.52) 27,15.52 27.14,15.67 36.01,15.67
PR24C: length 10.8
  TOP w0.102: BGA.R17 v1(25.92,15.52)
  BOTTOM w0.152: v1(25.92,15.52) 26.32,15.12 26.55,15.12 26.55,15.12 26.89,15.12 26.89,15.12 27.02,15.12 27.31,14.83 35.87,14.83
PR24D: length 14.7
  TOP w0.102: BGA.N14 v1(24.32,17.12)
  BOTTOM w0.152: 35.87,14.58 27.28,14.58 27.02,14.32 26.55,14.32 24.87,14.32 24.72,14.47 24.72,14.55 24.72,14.55 24.72,14.89 24.72,14.89 24.72,15.35 24.72,15.35 24.72,15.69 24.72,15.69 24.72,16.15 24.72,16.15 24.72,16.49 24.49,16.72 24.47,16.72 24.32,16.87 v1(24.32,17.12)
PR25A: length 13.1
  TOP w0.102: BGA.P15 v1(24.32,16.32)
  L4_SIGNAL w0.152: v1(24.32,16.32) 24.72,15.92 25.29,15.92 25.52,15.69 25.52,15.35 25.75,15.12 26.09,15.12 27.58,15.12 27.72,14.97 36.12,14.97
PR25B: length 9.9
  TOP w0.102: BGA.U18 v1(26.72,14.72)
  L4_SIGNAL w0.152: 36.01,14.72 v1(26.72,14.72)
PR25C: length 10.6
  TOP w0.102: BGA.R16 v1(25.12,15.52)
  L3_SIGNAL w0.152: 25.52,5.63 25.52,15.12 v1(25.12,15.52)
PR25D: length 9.7
  TOP w0.102: BGA.T17 v1(25.92,14.72)
  L3_SIGNAL w0.152: 25.77,5.63 25.77,14.21 25.92,14.36 v1(25.92,14.72)
PT9A: length 8.4
  TOP w0.152: BGA.A2 14.32,27.47 14.47,27.61 14.47,35.47
PT9B: length 9.3
  TOP w0.152: 14.72,35.47 14.72,26.72 BGA.B3
PT9C: length 12.7
  TOP w0.102: BGA.D4 v1(15.52,24.32)
  L4_SIGNAL w0.152: 14.57,35.47 14.57,26.57 14.22,26.22 14.22,25.06 14.55,24.72 14.89,24.72 15.29,24.32 v1(15.52,24.32)
PT9D: length 13.3
  TOP w0.102: BGA.E5 v1(16.32,23.52)
  L4_SIGNAL w0.152: v1(16.32,23.52) 15.92,23.92 15.92,24.49 15.69,24.72 15.67,24.72 15.35,24.72 15.12,24.95 15.12,26.31 14.82,26.61 14.82,35.47
PT10A: length 10.5
  TOP w0.102: BGA.C3 v1(14.72,25.12)
  L3_SIGNAL w0.152: 5.21,26.1 13.19,26.1 14.16,25.12 v1(14.72,25.12)
PT10B: length 11.4
  TOP w0.102: BGA.C4 v1(15.52,25.12)
  L3_SIGNAL w0.152: 5.21,26.35 13.29,26.35 14.12,25.52 15.12,25.52 v1(15.52,25.12)
PT10C: length 14.8
  TOP w0.102: BGA.F7 v1(18.72,23.52)
  L4_SIGNAL w0.152: v1(18.72,23.52) 18.32,23.92 16.92,23.92 16.72,24.12 16.72,24.49 16.49,24.72 16.15,24.72 15.92,24.95 15.92,26.32 16.21,26.61 16.21,35.49
PT10D: length 12
  TOP w0.102: BGA.E6 v1(17.12,24.32)
  L4_SIGNAL w0.152: 16.47,35.49 16.47,26.63 16.72,26.37 16.72,24.95 17.12,24.55 v1(17.12,24.32)
PT11A: length 8.4
  TOP w0.152: BGA.A3 15.12,27.43 15.27,27.57 15.27,35.49
PT11B: length 9.3
  TOP w0.152: 15.52,35.49 15.52,26.72 BGA.B4
PT11C: length 12.1
  TOP w0.102: BGA.D5 v1(16.32,24.32)
  L3_SIGNAL w0.152: 15.45,35.47 15.45,26.43 15.92,25.96 15.92,24.72 v1(16.32,24.32)
PT11D: length 10.5
  TOP w0.102: BGA.B5 v1(16.32,25.92)
  L3_SIGNAL w0.152: v1(16.32,25.92) 15.7,26.54 15.7,35.56
PT12A: length 8.5
  TOP w0.152: 16.19,35.49 16.19,27.39 BGA.A4
PT12B: length 8.5
  TOP w0.152: BGA.A5 16.44,27.4 16.44,35.49
PT13A: length 11.2
  TOP w0.102: BGA.C5 v1(16.32,25.12)
  BOTTOM w0.152: v1(16.32,25.12) 15.92,25.52 15.92,26.15 16.22,26.45 16.22,35.48
PT13B: length 11.2
  TOP w0.102: BGA.D6 v1(17.12,25.12)
  BOTTOM w0.152: 16.47,35.48 16.47,26.52 16.72,26.27 16.72,25.52 v1(17.12,25.12)
PT14A: length 9.3
  TOP w0.152: BGA.B6 17.12,26.72 17.12,35.48
PT14B: length 8.4
  TOP w0.152: BGA.A6 17.52,27.47 17.37,27.61 17.37,35.48
PT14C: length 11.1
  TOP w0.102: BGA.D7 v1(17.92,25.12)
  L4_SIGNAL w0.152: 17.37,35.48 17.37,26.54 17.52,26.39 17.52,26.04 17.52,26.03 17.52,25.52 v1(17.92,25.12)
PT14D: length 10.1
  TOP w0.102: BGA.C6 v1(17.12,25.92)
  L4_SIGNAL w0.152: 17.12,35.48 v1(17.12,25.92)
PT15A: length 8.4
  TOP w0.152: BGA.A7 18.32,27.47 18.17,27.61 18.17,35.48
PT15B: length 9.3
  TOP w0.152: 17.92,35.48 17.92,26.72 BGA.B7
PT16A: length 11.9
  TOP w0.102: BGA.D8 v1(18.72,25.12)
  L3_SIGNAL w0.152: v1(18.72,25.12) 18.32,25.52 17.75,25.52 17.52,25.75 17.52,26.22 17.2,26.54 17.2,35.47
PT16B: length 12.6
  TOP w0.102: BGA.E7 v1(17.92,24.32)
  L3_SIGNAL w0.152: 16.94,35.47 16.94,26.52 16.72,26.3 16.72,24.95 16.95,24.72 17.52,24.72 v1(17.92,24.32)
PT17A: length 9.3
  TOP w0.152: BGA.B8 18.72,26.72 18.72,35.46
PT17B: length 8.4
  TOP w0.152: BGA.A8 19.12,27.47 19.02,27.57 19.02,35.46
PT17C: length 10.2
  TOP w0.102: BGA.C7 v1(17.92,25.92)
  L3_SIGNAL w0.152: 18.19,35.47 18.19,26.19 v1(17.92,25.92)
PT17D: length 10.2
  TOP w0.102: BGA.C8 v1(18.72,25.92)
  L3_SIGNAL w0.152: v1(18.72,25.92) 18.45,26.19 18.45,35.47
PT18A: length 8.4
  TOP w0.152: 19.77,35.46 19.77,27.61 19.92,27.47 BGA.A9
PT18B: length 9.3
  TOP w0.152: 19.52,35.46 19.52,26.72 BGA.B9
PT18C: length 12
  TOP w0.102: BGA.E8 v1(18.72,24.32)
  L4_SIGNAL w0.152: 18.62,35.46 18.62,26.52 18.32,26.22 18.32,25.29 18.32,24.72 v1(18.72,24.32)
PT18D: length 12.8
  TOP w0.102: BGA.F8 v1(19.52,23.52)
  L4_SIGNAL w0.152: 18.87,35.46 18.87,26.52 19.12,26.28 19.12,23.92 v1(19.52,23.52)
PT21A: length 8.4
  TOP w0.152: BGA.A10 20.72,27.47 20.57,27.61 20.57,35.46
PT21B: length 9.3
  TOP w0.152: BGA.B10 20.32,26.72 20.32,35.46
PT21C: length 10.3
  TOP w0.102: BGA.C9 v1(19.52,25.92)
  L3_SIGNAL w0.152: 19.36,35.6 19.37,35.58 19.37,26.41 19.52,26.26 v1(19.52,25.92)
PT21D: length 11.1
  TOP w0.102: BGA.D9 v1(19.52,25.12)
  L3_SIGNAL w0.152: 19.12,35.47 19.12,25.52 19.52,25.12 v1(19.52,25.12)
PT22A: length 10.2
  TOP w0.102: BGA.C10 v1(20.32,25.92)
  BOTTOM w0.152: 20.6,35.48 20.6,26.2 v1(20.32,25.92)
PT22B: length 10.2
  TOP w0.102: BGA.B11 v1(21.12,25.92)
  BOTTOM w0.152: 20.87,35.48 20.87,26.17 v1(21.12,25.92)
PT22C: length 12
  TOP w0.102: BGA.E9 v1(19.52,24.32)
  BOTTOM w0.152: 19.4,35.48 19.4,26.6 19.12,26.32 19.12,25.37 19.12,24.95 19.52,24.55 v1(19.52,24.32)
PT22D: length 11.2
  TOP w0.102: BGA.D10 v1(20.32,25.12)
  BOTTOM w0.152: 19.65,35.48 19.65,26.57 19.92,26.3 19.92,25.52 v1(20.32,25.12)
PT25A: length 9.3
  TOP w0.102: BGA.B12 v1(21.92,26.72)
  L3_SIGNAL w0.152: v1(21.92,26.72) 21.92,35.47
PT25B: length 11.1
  TOP w0.102: BGA.C11 v1(21.12,25.12)
  L3_SIGNAL w0.152: 21.67,35.47 21.67,27.12 21.52,26.98 BGA.C11 v1(21.12,25.12)
PT25C: length 13.6
  TOP w0.102: BGA.F9 v1(19.52,22.72)
  L4_SIGNAL w0.152: 20.17,35.46 20.17,26.57 19.92,26.32 BGA.F9 v1(19.52,22.72)
PT25D: length 12.8
  TOP w0.102: BGA.F10 v1(20.32,23.52)
  L4_SIGNAL w0.152: v1(20.32,23.52) 20.72,23.92 20.72,26.28 20.42,26.57 20.42,35.46
PT26A: length 8.5
  TOP w0.152: 21.82,35.46 21.82,27.42 21.52,27.12 BGA.A11
PT26B: length 8.4
  TOP w0.152: 22.07,35.46 22.07,27.37 BGA.A12
PT26C: length 14
  TOP w0.102: BGA.E10 v1(20.32,24.32)
  BOTTOM w0.152: 18.07,35.48 18.07,26.57 18.32,26.32 18.32,24.95 18.55,24.72 18.89,24.72 19.12,24.49 19.12,24.15 19.35,23.92 19.92,23.92 v1(20.32,24.32)
PT26D: length 16.4
  TOP w0.102: BGA.E11 v1(21.12,23.52)
  BOTTOM w0.152: v1(21.12,23.52) 20.72,23.12 20.15,23.12 19.35,23.12 19.12,23.35 19.12,23.69 18.89,23.92 17.75,23.92 17.52,24.15 17.52,26.25 17.82,26.55 17.82,35.48
PT27A: length 10.3
  TOP w0.102: BGA.C12 v1(21.92,25.92)
  L3_SIGNAL w0.152: 22.32,35.47 22.32,26.32 21.92,25.92 v1(21.92,25.92)
PT27B: length 10.2
  TOP w0.102: BGA.B13 v1(22.72,25.92)
  L3_SIGNAL w0.152: v1(22.72,25.92) 22.72,26.16 22.57,26.31 22.57,35.47
PT27C: length 12
  TOP w0.102: BGA.D11 v1(21.12,24.32)
  BOTTOM w0.152: v1(21.12,24.32) BGA.D11 21.52,26.72 21.52,26.95 21.81,27.24 21.81,35.45
PT27D: length 11.2
  TOP w0.102: BGA.D12 v1(21.92,25.12)
  BOTTOM w0.152: 22.06,35.45 22.06,27.28 22.32,27.02 22.32,25.52 v1(21.92,25.12)
PT28A: length 8.4
  TOP w0.152: 23.37,35.45 23.37,27.37 BGA.A13
PT28B: length 8.5
  TOP w0.152: BGA.A14 23.62,27.42 23.62,35.45
PT32A: length 15.1
  TOP w0.102: BGA.F11 v1(21.12,22.72)
  BOTTOM w0.152: v1(21.12,22.72) BGA.F11 21.52,23.69 21.75,23.92 22.09,23.92 22.32,24.15 22.32,24.49 22.55,24.72 22.89,24.72 23.12,24.95 23.12,25.29 23.35,25.52 23.69,25.52 23.92,25.75 23.92,26.09 23.92,26.27 23.67,26.52 23.67,35.45
